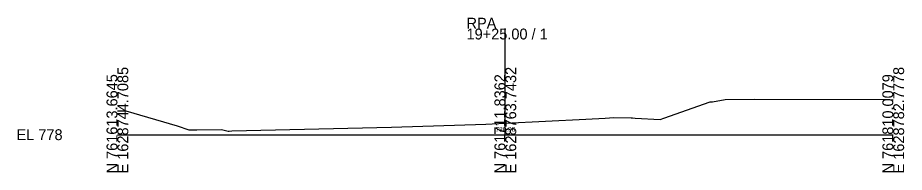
# Model space of a CAD drawing. Extents: x -26 to 203, y 990 to 7517.
# Drawn here: x -25.7 to 202.8, y 2490.3 to 2530.2 of the extents above; entities that cross this region are included whole.
import ezdxf

# ---------------------------------------------------------------- set-up
doc = ezdxf.new("R2010")
doc.units = 0
for name, color, linetype in [('Exist Cross Section Cell', 7, 'Continuous'), ('Exist XS Center Line Elevation Label', 7, 'Continuous'), ('Exist XS Ground Line', 7, 'Continuous')]:
    doc.layers.add(name, color=color, linetype=linetype)

msp = doc.modelspace()

# ---------------------------------------------------------------- linework, layer by layer
at = {"layer": 'Exist Cross Section Cell'}
for p, q in [((100, 2500), (100, 2527.36)), ((0, 2500), (100, 2500)), ((100, 2500), (200, 2500))]:
    msp.add_line(p, q, dxfattribs=at)
at = {"layer": 'Exist XS Ground Line'}
for p, q in [((140.87, 2504.24), (152.83, 2508.43)), ((152.83, 2508.43), (153.43, 2508.47)), ((153.43, 2508.47), (156.64, 2509.04)), ((156.64, 2509.04), (164.18, 2509.12)), ((164.18, 2509.12), (198.66, 2509.08)), ((198.66, 2509.08), (199.97, 2508.98)), ((0, 2506.12), (2.21, 2506.12)), ((2.21, 2506.12), (15.39, 2502.32)), ((70.62, 2501.93), (94.95, 2502.72)), ((94.95, 2502.72), (100, 2502.98)), ((100, 2502.98), (120.75, 2504.04)), ((120.75, 2504.04), (125.7, 2504.3)), ((125.7, 2504.3), (128.01, 2504.4)), ((128.01, 2504.4), (132.47, 2504.35)), ((132.47, 2504.35), (132.77, 2504.34)), ((132.77, 2504.34), (133.45, 2504.29)), ((133.45, 2504.29), (139.9, 2503.94)), ((139.9, 2503.94), (140.87, 2504.24)), ((15.39, 2502.32), (18.44, 2501.25)), ((18.44, 2501.25), (20.5, 2501.28)), ((20.5, 2501.28), (26.82, 2501.3)), ((26.82, 2501.3), (28.54, 2500.88)), ((28.54, 2500.88), (28.84, 2500.92)), ((28.84, 2500.92), (29.53, 2501.02)), ((29.53, 2501.02), (70.62, 2501.93))]:
    msp.add_line(p, q, dxfattribs=at)

# ---------------------------------------------------------------- texts
at = {"layer": 'Exist Cross Section Cell'}
for s, p in [('RPA', (90, 2527.36)), ('19+25.00 / 1', (90, 2524.56)), ('EL 778', (-26, 2498.6))]:
    msp.add_text(s, height=2.8, dxfattribs=at).set_placement(p)
for s, p in [('E 1628744.7085', (2.8, 2490)), ('E 1628763.7432', (102.8, 2490)), ('E 1628782.7778', (202.8, 2490)), ('N 761613.6645', (0, 2490)), ('N 761711.8362', (100, 2490)), ('N 761810.0079', (200, 2490))]:
    msp.add_text(s, height=2.8, rotation=90, dxfattribs=at).set_placement(p)
at = {"layer": 'Exist XS Center Line Elevation Label'}
msp.add_text('780.98', height=1.2, dxfattribs=at).set_placement((97.48, 2500.78))

doc.saveas('drawing.dxf')
